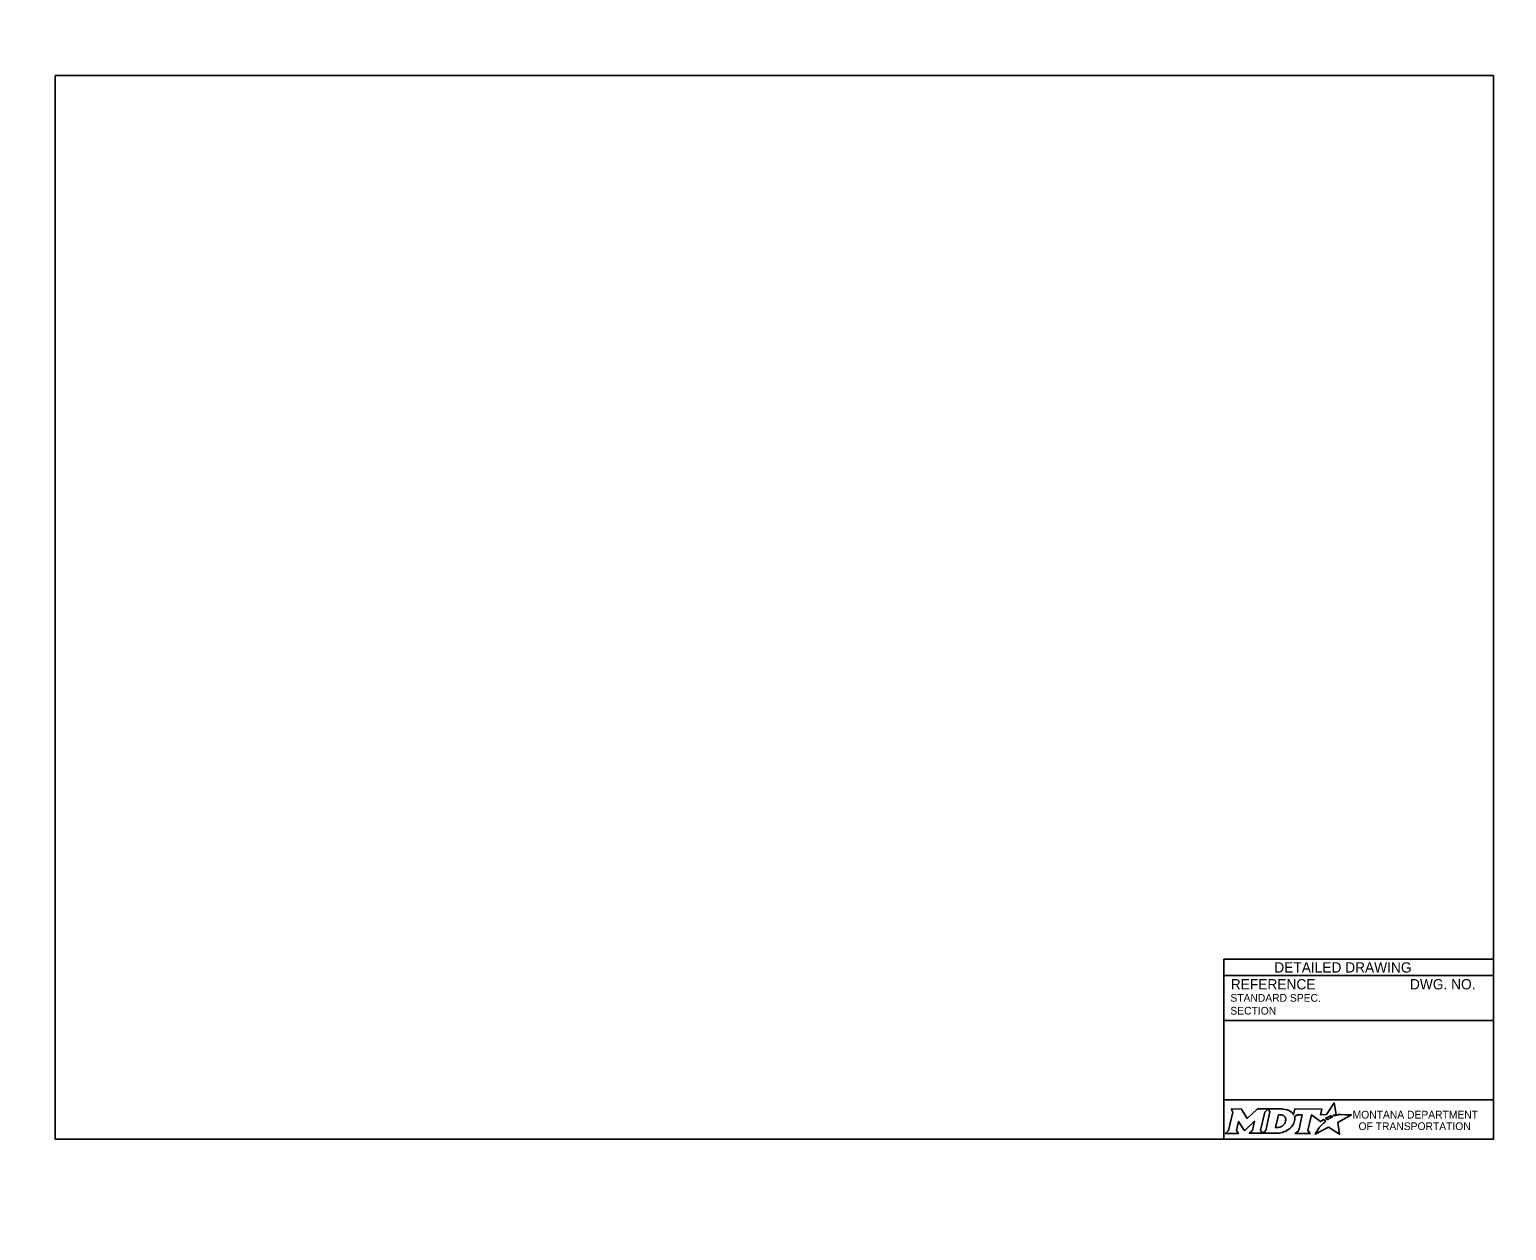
# Model space of a CAD drawing. Extents: x 49991 to 79985, y 47703 to 60542.
# Drawn here: x 50009.54 to 50021.04, y 49999.18 to 50008.52 of the extents above; entities that cross this region are included whole.
import ezdxf

# ---------------------------------------------------------------- set-up
doc = ezdxf.new("R2010")
doc.units = 0
for name, color, linetype in [('Default', 7, 'Continuous'), ('Level 1', 7, 'Continuous'), ('Level 4', 7, 'Continuous')]:
    doc.layers.add(name, color=color, linetype=linetype)

msp = doc.modelspace()

# ---------------------------------------------------------------- linework, layer by layer
at = {"layer": 'Default'}
for points in [[(50018.893, 50000.121), (50018.907, 50000.097), (50018.874, 49999.954), (50018.848, 49999.931), (50018.95, 49999.931), (50018.936, 49999.954), (50018.952, 50000.024), (50018.996, 49999.955), (50019.002, 49999.955), (50019.077, 50000.025), (50019.06, 49999.954), (50019.035, 49999.932), (50019.137, 49999.932), (50019.123, 49999.955), (50019.156, 50000.097)], [(50019.156, 50000.097), (50019.182, 50000.121), (50019.099, 50000.121), (50019.02, 50000.048), (50018.975, 50000.12), (50018.893, 50000.121)], [(50019.295, 50000.121), (50019.182, 50000.121), (50019.196, 50000.098), (50019.163, 49999.954), (50019.137, 49999.932), (50019.248, 49999.932)], [(50019.319, 50000.034), (50019.318, 50000.026), (50019.315, 50000.017), (50019.311, 50000.008), (50019.305, 50000.001), (50019.299, 49999.994), (50019.291, 49999.988), (50019.282, 49999.983), (50019.273, 49999.979), (50019.264, 49999.977), (50019.255, 49999.976), (50019.239, 49999.976), (50019.263, 50000.076), (50019.279, 50000.076), (50019.286, 50000.075), (50019.294, 50000.073), (50019.301, 50000.07), (50019.307, 50000.066), (50019.311, 50000.061), (50019.315, 50000.055), (50019.318, 50000.049), (50019.319, 50000.042), (50019.32, 50000.038), (50019.319, 50000.034)], [(50019.7, 50000.068), (50019.69, 50000.074), (50019.702, 50000.076), (50019.713, 50000.078), (50019.696, 50000.168), (50019.636, 50000.077), (50019.589, 50000.076), (50019.599, 50000.12), (50019.39, 50000.121), (50019.38, 50000.078), (50019.374, 50000.086)], [(50019.387, 50000.062), (50019.411, 50000.075), (50019.448, 50000.075), (50019.42, 49999.954), (50019.392, 49999.931), (50019.508, 49999.931), (50019.491, 49999.954), (50019.52, 50000.075), (50019.591, 50000.023), (50019.612, 50000.038), (50019.632, 50000.027)], [(50019.576, 49999.971), (50019.561, 49999.947), (50019.556, 49999.939), (50019.55, 49999.931), (50019.548, 49999.926), (50019.653, 49999.979), (50019.737, 49999.924), (50019.724, 50000.017), (50019.831, 50000.075), (50019.782, 50000.076), (50019.751, 50000.077), (50019.731, 50000.077), (50019.724, 50000.075), (50019.719, 50000.074), (50019.711, 50000.072), (50019.7, 50000.068)], [(50019.65, 50000.04), (50019.648, 50000.039), (50019.629, 50000.048), (50019.639, 50000.054), (50019.644, 50000.056), (50019.652, 50000.06), (50019.658, 50000.063), (50019.666, 50000.066), (50019.673, 50000.068), (50019.685, 50000.061), (50019.681, 50000.059), (50019.676, 50000.056), (50019.672, 50000.054), (50019.667, 50000.051), (50019.665, 50000.05), (50019.662, 50000.049), (50019.66, 50000.047), (50019.658, 50000.046), (50019.655, 50000.044), (50019.652, 50000.042), (50019.65, 50000.04)], [(50019.293, 49999.939), (50019.302, 49999.942), (50019.315, 49999.947), (50019.335, 49999.958)], [(50019.59, 49999.987), (50019.59, 49999.987)]]:
    msp.add_lwpolyline(points, dxfattribs=at)
for centre, radius, start, end in [((50019.319, 50000.042), 0.0709, 339.5329, 15.8582), ((50019.274, 50000.059), 0.118, 300.9103, 339.1383)]:
    msp.add_arc(centre, radius, start, end, dxfattribs=at)
for centre, major_axis, ratio, start_param, end_param in [((50019.293, 50000.073), (0.0834, -0.0037), 0.568097, 0.61298, 1.570796), ((50019.349, 50000.081), (0.0361, -0.0295), 0.469099, 1.225588, 1.570796), ((50019.583, 49999.979), (-0.00694, -0.00806), 0.008222, 0, 3.137361), ((50019.6, 49999.997), (-0.0098, -0.0102), 0.016458, 3.141593, 6.279097), ((50019.621, 50000.017), (-0.0112, -0.0097), 0.021651, 3.157348, 6.283185), ((50019.248, 50000.08), (0, 0.148), 0.987302, 3.139398, 3.456847)]:
    msp.add_ellipse(centre, major_axis=major_axis, ratio=ratio, start_param=start_param, end_param=end_param, dxfattribs=at)
at = {"layer": 'Level 1'}
for p, q in [((50021.038, 50008.524), (50021.038, 50008.524)), ((50009.537, 49999.736), (50009.537, 49999.736)), ((50016.9, 49999.176), (50016.9, 49999.176))]:
    msp.add_line(p, q, dxfattribs=at)
msp.add_lwpolyline([(50020.938, 50008.165), (50009.737, 50008.165), (50009.737, 49999.886), (50020.938, 49999.886)], close=True, dxfattribs=at)
at = {"layer": 'Level 4'}
for p, q in [((50020.938, 50001.286), (50018.838, 50001.286)), ((50018.838, 50001.286), (50018.838, 49999.886)), ((50020.938, 50001.161), (50018.838, 50001.161)), ((50019.332, 50000.886), (50019.332, 50000.886)), ((50020.574, 50000.946), (50020.574, 50000.946)), ((50020.938, 50000.811), (50018.838, 50000.811)), ((50019.888, 50000.562), (50019.888, 50000.562)), ((50020.938, 50000.193), (50018.838, 50000.193))]:
    msp.add_line(p, q, dxfattribs=at)

# ---------------------------------------------------------------- texts
at = {"layer": 'Default'}
for s, p in [('MONTANA DEPARTMENT', (50019.84, 50000.047)), ('OF TRANSPORTATION', (50019.886, 49999.957))]:
    msp.add_text(s, height=0.06, rotation=360, dxfattribs=at).set_placement(p)
at = {"layer": 'Level 4'}
for s, height, p in [('DETAILED DRAWING', 0.0799, (50019.23, 50001.183)), ('REFERENCE', 0.08, (50018.891, 50001.052)), ('DWG. NO.', 0.08, (50020.286, 50001.052)), ('STANDARD SPEC.', 0.06, (50018.888, 50000.956)), ('SECTION', 0.06, (50018.888, 50000.856))]:
    msp.add_text(s, height=height, dxfattribs=at).set_placement(p)

doc.saveas('drawing.dxf')
